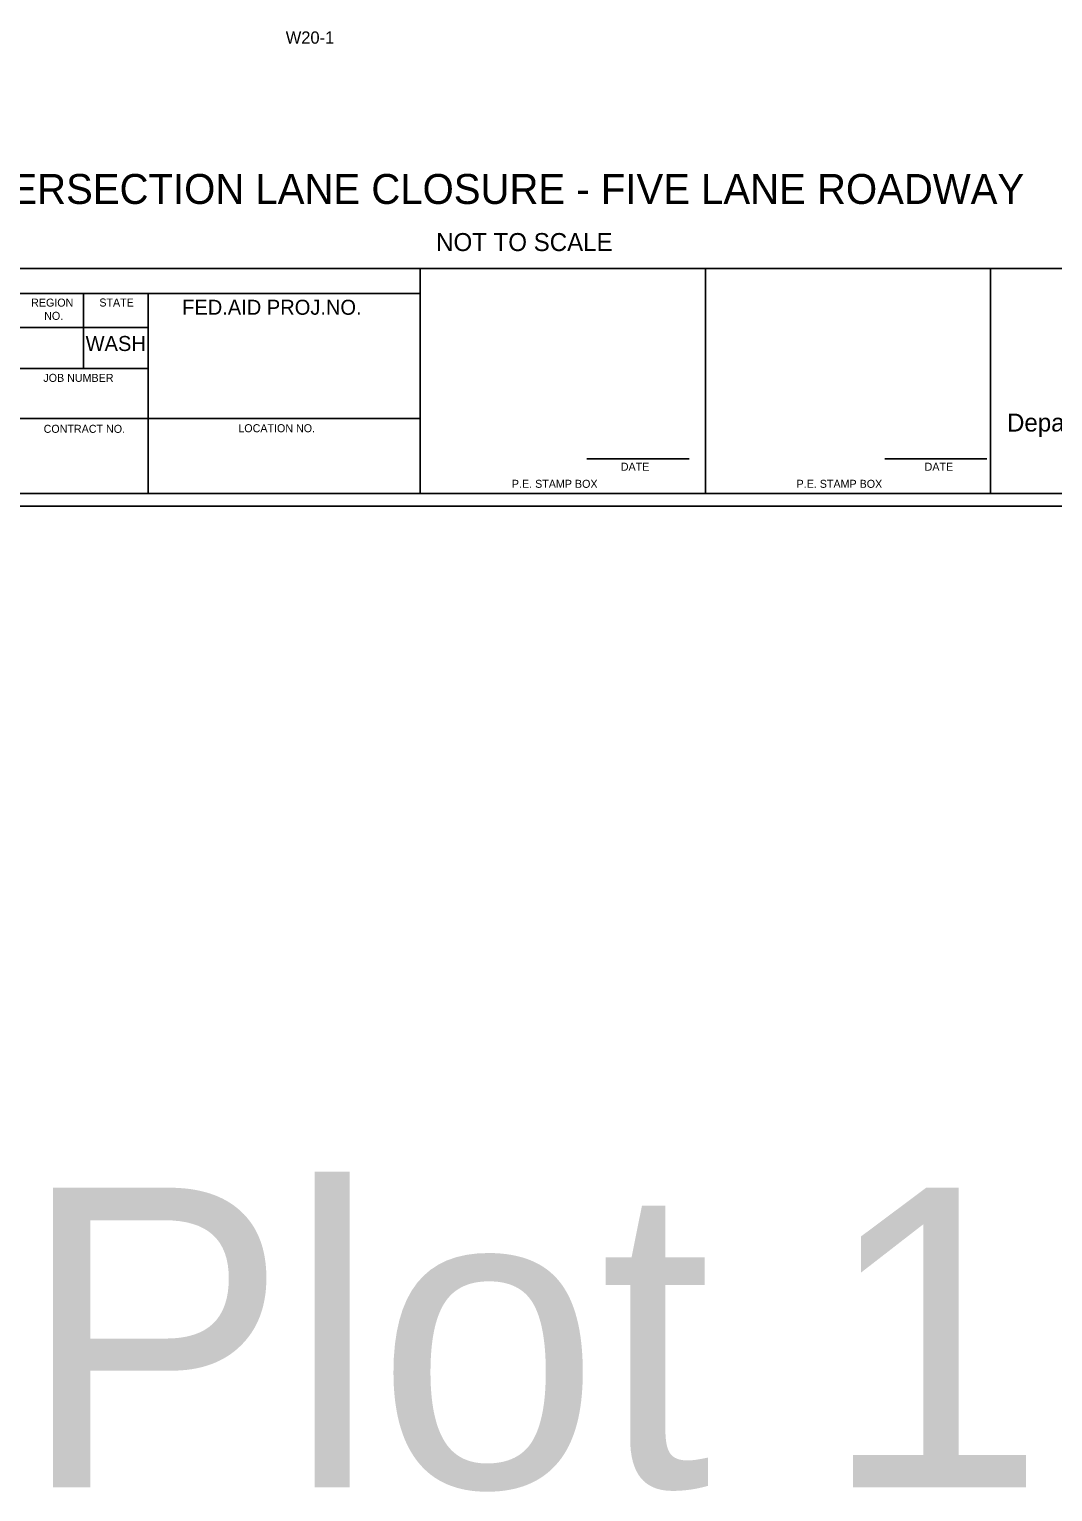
# Model space of a CAD drawing. Extents: x 99988 to 100172, y 99995 to 100047.
# Drawn here: x 100005.5 to 100010.62, y 99995.01 to 100002.32 of the extents above; entities that cross this region are included whole.
import ezdxf

# ---------------------------------------------------------------- set-up
doc = ezdxf.new("R2010")
doc.units = 0
for name, color, linetype in [('SH_DE_DetailHeading1Text', 7, 'Continuous'), ('SH_DE_DetailHeading3Text', 7, 'Continuous'), ('SH_GI_PlotLimits', 7, 'Continuous'), ('SH_GI_SheetBorder', 7, 'Continuous'), ('SH_GI_SheetLocationText', 7, 'Continuous'), ('SH_GI_SheetTextInCells', 7, 'Continuous'), ('TR_SN_WarningSigns', 7, 'Continuous')]:
    doc.layers.add(name, color=color, linetype=linetype)

msp = doc.modelspace()

# ---------------------------------------------------------------- linework, layer by layer
at = {"layer": 'SH_GI_PlotLimits'}
msp.add_lwpolyline([(99999.3125, 99999.9375), (100015.8125, 99999.9375), (100015.8125, 100010.4375), (99999.3125, 100010.4375)], close=True, dxfattribs=at)
at = {"layer": 'SH_GI_SheetBorder'}
for p, q in [((100000, 100001.1259), (100015.75, 100001.1259)), ((100007.4566, 100000), (100007.4566, 100001.1259)), ((100008.8828, 100000), (100008.8828, 100001.1259)), ((100010.3089, 100001.1259), (100010.3089, 100000)), ((100000, 100001.0008), (100007.4566, 100001.0008)), ((100005.7719, 100000.6255), (100005.7719, 100001.0008)), ((100006.0956, 100000), (100006.0956, 100001.0008)), ((100006.0958, 100000.831), (100005.4466, 100000.831)), ((100006.0958, 100000.6255), (100005.4466, 100000.6255)), ((100007.4566, 100000.3753), (100005.4466, 100000.3753)), ((100008.2903, 100000.1733), (100008.802, 100000.1733)), ((100009.7797, 100000.1733), (100010.2914, 100000.1733)), ((100000, 100000), (100015.75, 100000))]:
    msp.add_line(p, q, dxfattribs=at)

# ---------------------------------------------------------------- texts
at = {"layer": 'SH_DE_DetailHeading1Text'}
msp.add_text('INTERSECTION LANE CLOSURE - FIVE LANE ROADWAY', height=0.150001, dxfattribs=at).set_placement((100005.083, 100001.4489))
at = {"layer": 'SH_DE_DetailHeading3Text'}
msp.add_text('NOT TO SCALE', height=0.09, dxfattribs=at).set_placement((100007.5359, 100001.2132))
at = {"layer": 'SH_GI_SheetLocationText'}
msp.add_text('Plot 1', height=1.5, dxfattribs=at).set_placement((100005.4547, 99995.0267))
at = {"layer": 'SH_GI_SheetTextInCells'}
for s, height, p in [('REGION', 0.04003, (100005.5099, 100000.9352)), ('STATE', 0.04003, (100005.8511, 100000.9357)), ('FED.AID PROJ.NO.', 0.07506, (100006.2652, 100000.8945)), ('NO.', 0.04003, (100005.5752, 100000.869)), ('WASH', 0.07506, (100005.7826, 100000.7131)), ('JOB NUMBER', 0.04003, (100005.5712, 100000.5587)), ('CONTRACT NO.', 0.040032, (100005.5725, 100000.3037)), ('LOCATION NO.', 0.040032, (100006.5465, 100000.3067)), ('Department of Transportation', 0.090072, (100010.3916, 100000.3101)), ('DATE', 0.04003, (100008.4597, 100000.1141)), ('DATE', 0.04003, (100009.9794, 100000.1141)), ('P.E. STAMP BOX', 0.040032, (100007.915, 100000.0286)), ('P.E. STAMP BOX', 0.040032, (100009.339, 100000.0286))]:
    msp.add_text(s, height=height, dxfattribs=at).set_placement(p)
at = {"layer": 'TR_SN_WarningSigns'}
msp.add_text('W20-1', height=0.06152, dxfattribs=at).set_placement((100006.7837, 100002.2507))

doc.saveas('drawing.dxf')
